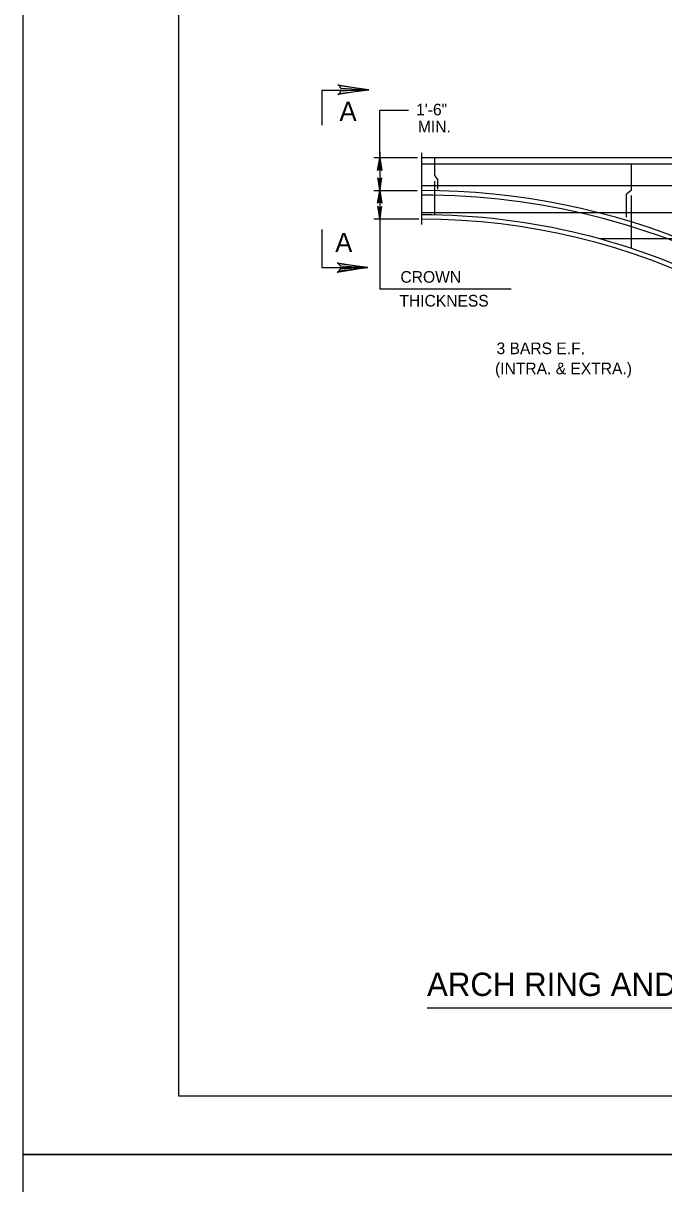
# Model space of a CAD drawing. Extents: x 639028 to 639883, y 298843 to 300031.
# Drawn here: x 639027.7 to 639192.5, y 299429.6 to 299727.9 of the extents above; entities that cross this region are included whole.
import ezdxf

# ---------------------------------------------------------------- set-up
doc = ezdxf.new("R2010")
doc.units = 0
for name, color, linetype in [('2', 7, 'Continuous'), ('53', 7, 'Continuous'), ('PLT-BNDY', 7, 'Continuous')]:
    doc.layers.add(name, color=color, linetype=linetype)

msp = doc.modelspace()

# ---------------------------------------------------------------- linework, layer by layer
at = {"layer": '2'}
for p, q in [((639067.74, 299452.08), (639067.74, 300016.08)), ((639104.54, 299710.68), (639104.54, 299701.74)), ((639104.54, 299710.68), (639114.31, 299710.68)), ((639119.42, 299693.35), (639119.42, 299705.45)), ((639126.84, 299705.45), (639119.42, 299705.45)), ((639119.42, 299694.73), (639119.42, 299684.83)), ((639130.28, 299676.17), (639130.28, 299694.59)), ((639129.18, 299693.35), (639117.9, 299693.35)), ((639313.78, 299693.35), (639130.28, 299693.35)), ((639310.54, 299691.7), (639130.28, 299691.7)), ((639133.58, 299688.68), (639133.58, 299693.35)), ((639184.18, 299684.97), (639184.18, 299691.7)), ((639133.58, 299688.68), (639134.4, 299687.58)), ((639310.54, 299686.07), (639130.28, 299686.07)), ((639133.58, 299678.64), (639133.58, 299687.3)), ((639134.4, 299685.24), (639134.4, 299687.58)), ((639129.04, 299684.83), (639117.9, 299684.83)), ((639119.42, 299684.83), (639119.42, 299675.07)), ((639184.18, 299684.97), (639182.94, 299684)), ((639182.94, 299678.09), (639182.94, 299684)), ((639184.18, 299669.98), (639184.18, 299683.59)), ((639217.32, 299679.19), (639130.28, 299679.19)), ((639129.45, 299677.54), (639117.9, 299677.54)), ((639119.42, 299677.54), (639119.42, 299659.53)), ((639104.54, 299674.87), (639104.54, 299665.11)), ((639217.18, 299672.45), (639176.2, 299672.45)), ((639104.54, 299665.11), (639114.31, 299665.11)), ((639153.24, 299659.53), (639119.42, 299659.53)), ((639853.74, 299452.08), (639067.74, 299452.08))]:
    msp.add_line(p, q, dxfattribs=at)
for points in [[(639109.08, 299711.78), (639109.36, 299711.23), (639116.64, 299710.82), (639109.08, 299711.78), (639108.67, 299712.06), (639116.64, 299710.82), (639109.36, 299710.41), (639109.08, 299709.86), (639116.64, 299710.82), (639108.67, 299709.58), (639109.08, 299709.86)], [(639119.03, 299690.21), (639119.26, 299690.34), (639119.43, 299693.32), (639119.03, 299690.21), (639118.9, 299690.05), (639119.43, 299693.32), (639119.57, 299690.34), (639119.8, 299690.22), (639119.43, 299693.32), (639119.96, 299690.05), (639119.8, 299690.22)], [(639119.03, 299687.97), (639119.26, 299687.85), (639119.43, 299684.86), (639119.03, 299687.97), (639118.89, 299688.13), (639119.43, 299684.86), (639119.57, 299687.85), (639119.8, 299687.96), (639119.43, 299684.86), (639119.96, 299688.13), (639119.8, 299687.96)], [(639119.03, 299681.82), (639119.26, 299681.95), (639119.43, 299684.93), (639119.03, 299681.82), (639118.89, 299681.67), (639119.43, 299684.93), (639119.57, 299681.95), (639119.8, 299681.83), (639119.43, 299684.93), (639119.96, 299681.67), (639119.8, 299681.83)], [(639119.03, 299680.69), (639119.26, 299680.56), (639119.43, 299677.57), (639119.03, 299680.69), (639118.89, 299680.84), (639119.43, 299677.57), (639119.57, 299680.56), (639119.8, 299680.67), (639119.43, 299677.57), (639119.96, 299680.84), (639119.8, 299680.67)], [(639108.81, 299666.07), (639109.22, 299665.52), (639116.37, 299665.11), (639108.81, 299666.07), (639108.53, 299666.35), (639116.37, 299665.11), (639109.22, 299664.7), (639108.94, 299664.29), (639116.37, 299665.11), (639108.53, 299663.87), (639108.94, 299664.29)]]:
    msp.add_lwpolyline(points, dxfattribs=at)
for centre, major_axis, ratio, start_param in [((639130.23, 299520.96), (-174.13, 0), 0.941368, 3.870612), ((639130.23, 299520.96), (-172.99, 0), 0.940984, 4.190973), ((639130.23, 299526.64), (-162.22, 0), 0.937063, 4.199675), ((639130.23, 299526.64), (-161.08, 0), 0.93662, 3.714425)]:
    msp.add_ellipse(centre, major_axis=major_axis, ratio=ratio, start_param=start_param, end_param=4.712389, dxfattribs=at)
at = {"layer": '53'}
msp.add_line((639131.6, 299474.85), (639331.39, 299474.85), dxfattribs=at)
at = {"layer": 'PLT-BNDY'}
for points in [[(639027.74, 300031.08), (639868.74, 300031.08), (639868.74, 299437.08), (639027.74, 299437.08)], [(639027.74, 299437.08), (639868.74, 299437.08), (639868.74, 298843.08), (639027.74, 298843.08)]]:
    msp.add_lwpolyline(points, close=True, dxfattribs=at)

# ---------------------------------------------------------------- texts
at = {"layer": '2'}
for p in [(639109.08, 299702.8), (639107.98, 299669.08)]:
    msp.add_text('A', height=4.95, rotation=360, dxfattribs=at).set_placement(p)
for s, height, p in [('1\'-6"', 3, (639128.79, 299704.22)), ('MIN.', 3, (639129.26, 299699.83)), ('CROWN', 3, (639124.77, 299661.2)), ('THICKNESS', 3, (639124.5, 299655.08)), ('3 BARS E.F.', 2.9997, (639149.48, 299642.84)), ('(INTRA. & EXTRA.)', 2.9997, (639149.09, 299637.67))]:
    msp.add_text(s, height=height, dxfattribs=at).set_placement(p)
at = {"layer": '53'}
msp.add_text('ARCH RING AND SPANDREL WALL DETAIL', height=6, dxfattribs=at).set_placement((639131.6, 299477.85))

doc.saveas('drawing.dxf')
